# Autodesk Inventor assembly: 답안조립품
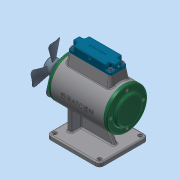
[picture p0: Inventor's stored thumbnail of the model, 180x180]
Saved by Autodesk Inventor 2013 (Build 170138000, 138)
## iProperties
Created: 2019-07
Part Number: 답안조립품
Document SubType Name: Assembly
Designer: dgall
Author: dgall
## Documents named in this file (19)
- C:\Users\dgall\Desktop\390704V1019\답안조립품.iam
- C:\Users\dgall\Desktop\390704V1019\본체.ipt
- C:\Users\dgall\Desktop\390704V1019\뒤커버.ipt
- C:\Users\dgall\Desktop\390704V1019\베어링 6203.ipt
- C:\Users\dgall\Desktop\390704V1019\축.ipt
- C:\Users\dgall\Desktop\390704V1019\앞커버.ipt
- C:\Users\dgall\Desktop\390704V1019\오일실 17 30 8.ipt
- C:\Users\dgall\Desktop\390704V1019\키 5 x 5 x 18.ipt
- C:\Users\dgall\Desktop\390704V1019\볼트 M4 x 12.ipt
- C:\Users\dgall\Desktop\390704V1019\팬날개.ipt
- 팬날개.ipt
- C:\Users\dgall\Desktop\390704V1019\멈춤나사 M4 x 5.ipt
- C:\Users\dgall\Desktop\390704V1019\부시.ipt
- C:\Users\dgall\Desktop\390704V1019\슬라이드.ipt
- C:\Users\dgall\Desktop\390704V1019\스프링1.ipt
- C:\Users\dgall\Desktop\390704V1019\스프링2.ipt
- C:\Users\dgall\Desktop\390704V1019\스프링3.ipt
- C:\Users\dgall\Desktop\390704V1019\헤더커버.ipt
- C:\Users\dgall\Desktop\390704V1019\볼트 M4 x 16.ipt
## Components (1 placed, 1 different names)
1. 헤더커버:1
